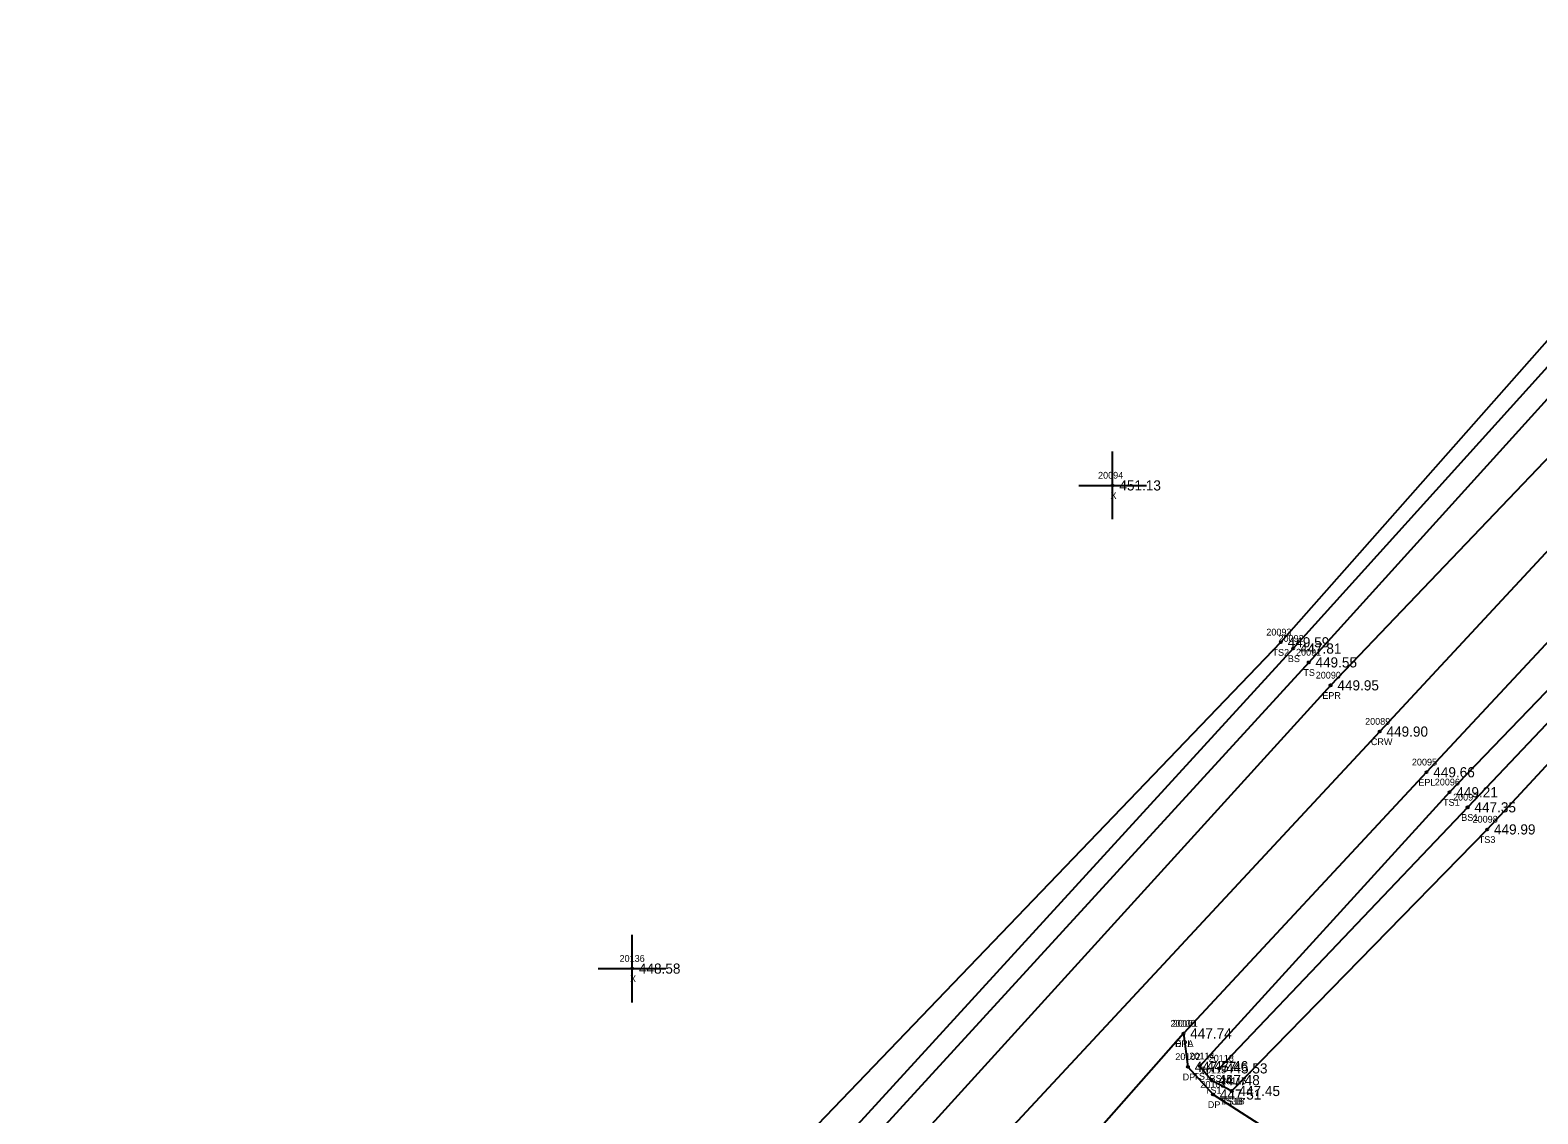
# Model space of a CAD drawing. Extents: x 1763022 to 1764007, y 824123 to 825394.
# Drawn here: x 1763483.2 to 1763705.9, y 825006.9 to 825166.9 of the extents above; entities that cross this region are included whole.
import ezdxf

# ---------------------------------------------------------------- set-up
doc = ezdxf.new("R2010")
doc.units = 0
for name, color, linetype in [('RD_DTM_BkLn1', 7, 'Continuous'), ('RD_DTM_BkLn2', 7, 'Continuous'), ('RD_DTM_BkLn_txCode', 7, 'Continuous'), ('RD_EX_Driveway', 7, 'Continuous'), ('RD_EX_Driveway_txCode', 7, 'Continuous'), ('RD_EX_Misc', 7, 'Continuous'), ('RD_EX_Misc_txCode', 7, 'Continuous'), ('RD_EX_Road', 7, 'Continuous'), ('RD_EX_Road_txCode', 7, 'Continuous'), ('RD_EX_TX_Driveway_ELEV', 7, 'Continuous'), ('RD_EX_TX_Misc_ELEV', 7, 'Continuous'), ('RD_EX_TX_Road_ELEV', 7, 'Continuous'), ('RD_HC_Survey_ELEV', 7, 'Continuous'), ('RD_HC_Survey_txCode', 7, 'Continuous'), ('RD_SMD_Locator', 7, 'Continuous')]:
    doc.layers.add(name, color=color, linetype=linetype)

msp = doc.modelspace()

# ---------------------------------------------------------------- linework, layer by layer
at = {"layer": 'RD_DTM_BkLn1'}
msp.add_lwpolyline([(1763957.85, 825358.99), (1763889.22, 825284.86), (1763820.79, 825210.5), (1763751.37, 825137.44), (1763682.52, 825063.34), (1763613.99, 824989.62), (1763581.46, 824952.08), (1763550.2, 824912.66), (1763519.29, 824872.78), (1763491.16, 824832.15)], dxfattribs=at)
at = {"layer": 'RD_DTM_BkLn2'}
for points in [[(1763968.07, 825349.7), (1763900.27, 825275.17), (1763832.66, 825200.26), (1763762.42, 825126.65), (1763692.83, 825054.38), (1763655.96, 825013.92), (1763657.67, 825011.86), (1763660.66, 825010.25)], [(1763969.49, 825348.41), (1763901.67, 825274.17), (1763835.08, 825198.5), (1763765.09, 825125.58), (1763695.51, 825052.15), (1763658.81, 825013.59)], [(1763971.84, 825347.08), (1763903.21, 825271.94), (1763836.32, 825197.24), (1763767.44, 825123.48), (1763698.39, 825048.89), (1763660.66, 825010.25)], [(1763745.88, 825160.71), (1763743.95, 825161.45), (1763741.33, 825161.23), (1763734.19, 825151.51), (1763667.93, 825076.53), (1763598.29, 825004), (1763566.28, 824964.92), (1763532.04, 824927.7), (1763520.45, 824914.1), (1763512.76, 824909.25), (1763510.52, 824906.49), (1763509.94, 824903.93)], [(1763745.88, 825160.71), (1763746.84, 825156.51), (1763744.4, 825153.55), (1763739.17, 825147.71), (1763672.03, 825073.56), (1763603.55, 824998.75), (1763569.03, 824962.49), (1763535.77, 824923.77), (1763524.58, 824910.39), (1763517.67, 824903.1), (1763511.98, 824902.34), (1763509.94, 824903.93)], [(1763743.62, 825158.44), (1763736.6, 825149.65), (1763669.73, 825075.6), (1763601.09, 825000.55), (1763567.43, 824963.88), (1763533.82, 824926.24), (1763521.76, 824912.79), (1763514.73, 824907.04), (1763512.63, 824905.46)]]:
    msp.add_lwpolyline(points, dxfattribs=at)
at = {"layer": 'RD_EX_Driveway'}
msp.add_lwpolyline([(1763653.53, 825018.75), (1763654.2, 825013.82), (1763657.9, 825009.73), (1763667.44, 825003.61), (1763659.62, 824995.13), (1763650.65, 825000.23), (1763642.92, 825000.89), (1763637.74, 825000.8)], dxfattribs=at)
at = {"layer": 'RD_EX_Misc'}
for p, q in [((1763643.07, 825094.7), (1763643.07, 825104.7)), ((1763638.07, 825099.7), (1763648.07, 825099.7)), ((1763572.11, 825023.33), (1763572.11, 825033.33)), ((1763567.11, 825028.33), (1763577.11, 825028.33))]:
    msp.add_line(p, q, dxfattribs=at)
at = {"layer": 'RD_EX_Road'}
for points in [[(1763951.03, 825365.44), (1763882.12, 825291.59), (1763813.3, 825217.44), (1763784.22, 825184.64), (1763754.38, 825152.48), (1763744.67, 825142.84), (1763675.27, 825070.17), (1763607.46, 824995.53), (1763574.27, 824958.09), (1763542.37, 824919.2), (1763512.11, 824877.96), (1763483.2, 824837.35)], [(1763963.89, 825353.59), (1763895.68, 825279.08), (1763827.34, 825205.22), (1763758.38, 825131.33), (1763689.43, 825057.33), (1763653.53, 825018.75), (1763637.74, 825000.8), (1763620.71, 824983.81), (1763588.78, 824946.6), (1763557.13, 824907.38), (1763526.52, 824867.67), (1763498.43, 824827.25)]]:
    msp.add_lwpolyline(points, dxfattribs=at)
at = {"layer": 'RD_SMD_Locator'}
for centre in [(1763643.07, 825099.7), (1763667.93, 825076.53), (1763669.73, 825075.6), (1763672.03, 825073.56), (1763675.27, 825070.17), (1763682.52, 825063.34), (1763689.43, 825057.33), (1763692.83, 825054.38), (1763695.51, 825052.15), (1763698.39, 825048.89), (1763572.11, 825028.33), (1763653.53, 825018.75), (1763653.53, 825018.75), (1763654.2, 825013.82), (1763655.96, 825013.92), (1763658.81, 825013.59), (1763657.67, 825011.86), (1763660.66, 825010.25), (1763660.66, 825010.25), (1763657.9, 825009.73)]:
    msp.add_circle(centre, 0.15, dxfattribs=at)

# ---------------------------------------------------------------- texts
at = {"layer": 'RD_DTM_BkLn_txCode'}
for s, p in [('20093', (1763665.77, 825077.53)), ('20092', (1763667.57, 825076.6)), ('TS2', (1763666.68, 825074.53)), ('20091', (1763670.16, 825074.56)), ('BS', (1763668.95, 825073.6)), ('TS', (1763671.24, 825071.56)), ('20096', (1763690.65, 825055.38)), ('TS1', (1763691.87, 825052.38)), ('20097', (1763693.35, 825053.15)), ('BS1', (1763694.56, 825050.15)), ('20098', (1763696.23, 825049.89)), ('TS3', (1763697.15, 825046.89)), ('20114', (1763654.41, 825014.92)), ('20118', (1763657.26, 825014.59)), ('TS1', (1763655, 825011.92)), ('20115', (1763656.12, 825012.86)), ('BS1B', (1763657.39, 825011.59)), ('TS1', (1763656.71, 825009.86)), ('20116', (1763659.09, 825011.25)), ('20117', (1763659.11, 825011.25)), ('TS3B', (1763658.95, 825008.25)), ('TS1B', (1763659.23, 825008.25))]:
    msp.add_text(s, height=1, dxfattribs=at).set_placement(p)
at = {"layer": 'RD_EX_Driveway_txCode'}
for s, p in [('20101', (1763651.94, 825019.75)), ('DPA', (1763652.27, 825016.75)), ('20102', (1763652.33, 825014.82)), ('DP', (1763653.42, 825011.82)), ('20103', (1763656.03, 825010.73)), ('DP', (1763657.13, 825007.73))]:
    msp.add_text(s, height=1, dxfattribs=at).set_placement(p)
at = {"layer": 'RD_EX_Misc_txCode'}
for s, p in [('20094', (1763640.92, 825100.7)), ('X', (1763642.76, 825097.7)), ('20136', (1763570.25, 825029.33)), ('X', (1763571.8, 825026.33))]:
    msp.add_text(s, height=1, dxfattribs=at).set_placement(p)
at = {"layer": 'RD_EX_Road_txCode'}
for s, p in [('20090', (1763673.07, 825071.17)), ('EPR', (1763674.04, 825068.17)), ('20095', (1763687.27, 825058.33)), ('EPL', (1763688.22, 825055.33)), ('20100', (1763651.62, 825019.75)), ('EPL', (1763652.33, 825016.75))]:
    msp.add_text(s, height=1, dxfattribs=at).set_placement(p)
at = {"layer": 'RD_EX_TX_Driveway_ELEV'}
for s, p in [('447.74', (1763654.53, 825018)), ('447.57', (1763655.2, 825013.07)), ('447.51', (1763658.9, 825008.98))]:
    msp.add_text(s, height=1.5, dxfattribs=at).set_placement(p)
at = {"layer": 'RD_EX_TX_Misc_ELEV'}
for s, p in [('451.13', (1763644.07, 825098.95)), ('449.59', (1763668.93, 825075.78)), ('447.81', (1763670.73, 825074.85)), ('449.55', (1763673.03, 825072.81)), ('449.21', (1763693.83, 825053.63)), ('447.35', (1763696.51, 825051.4)), ('449.99', (1763699.39, 825048.14)), ('448.58', (1763573.11, 825027.58)), ('447.46', (1763656.96, 825013.17)), ('447.48', (1763658.67, 825011.11)), ('445.53', (1763659.81, 825012.84)), ('447.45', (1763661.66, 825009.5)), ('447.45', (1763661.66, 825009.5))]:
    msp.add_text(s, height=1.5, dxfattribs=at).set_placement(p)
at = {"layer": 'RD_EX_TX_Road_ELEV'}
for s, p in [('449.95', (1763676.27, 825069.42)), ('449.66', (1763690.43, 825056.58)), ('447.74', (1763654.53, 825018))]:
    msp.add_text(s, height=1.5, dxfattribs=at).set_placement(p)
at = {"layer": 'RD_HC_Survey_ELEV'}
msp.add_text('449.90', height=1.5, dxfattribs=at).set_placement((1763683.52, 825062.59))
at = {"layer": 'RD_HC_Survey_txCode'}
for s, p in [('20089', (1763680.36, 825064.34)), ('CRW', (1763681.21, 825061.34))]:
    msp.add_text(s, height=1, dxfattribs=at).set_placement(p)

doc.saveas('drawing.dxf')
